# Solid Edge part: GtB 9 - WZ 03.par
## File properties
Author: Carsten
Template: Normal.par
Last saved by: Carsten
Revision: 2
Application: Solid Edge
Genauigkeit: 0,990
Teilflächenrmatvorlage: Model Default
Coef. of Thermal Exp: 0.0
Thermal Conductivity: 0.0
Specific Heat: 0.0
Modulus of Elasticity: 0.0
Poission's Ratio: 0.0
Yield Stress: 0.0
Ultimate Stress: 0.0
Elongation: 0.0
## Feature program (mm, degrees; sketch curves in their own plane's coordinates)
sketch for "unnamed Protrusion 1" plane through (0, 0, 0) normal (1, 0, 0) x-axis (0, 1, 0)
  line (-25.836, 43.4801) -> (-25.836, -41.5199)
  line (-25.836, -41.5199) -> (29.164, -41.5199)
  line (29.164, -41.5199) -> (29.164, 43.4801)
  line (29.164, 43.4801) -> (-25.836, 43.4801)
extrude "unnamed Protrusion 1" add finite 60 along -normal
sketch for "Ausschnitt_1" #1 plane through (0, 1.664, 0.9801) normal (1, 0, 0) x-axis (0, 1, 0)
  line (27.5, -42.5) -> (27.5, -27.5)
  line (27.5, -27.5) -> (17.5, -27.5)
  line (17.5, -27.5) -> (17.5, -42.5)
  line (17.5, -42.5) -> (27.5, -42.5)
sketch for "Ausschnitt_1" #2 plane through (0, 1.664, 0.9801) normal (1, 0, 0) x-axis (0, 1, 0)
  line (-27.5, -42.5) -> (-17.5, -42.5)
  line (-17.5, -42.5) -> (-17.5, -27.5)
  line (-17.5, -27.5) -> (-27.5, -27.5)
  line (-27.5, -27.5) -> (-27.5, -42.5)
extrude "Ausschnitt_1" cut finite 146.05 along -normal
sketch for "Ausschnitt_2" plane through (0, 1.664, 0.9801) normal (1, 0, 0) x-axis (0, 1, 0)
  line (-10, -42.5) -> (-10, -32.5)
  line (-10, -32.5) -> (10, -32.5)
  line (10, -32.5) -> (10, -42.5)
  line (10, -42.5) -> (-10, -42.5)
  dimension (linear) = 10
  dimension (linear) = 10
extrude "Ausschnitt_2" cut finite 107.95 along -normal
sketch for "Ausschnitt_3" #1 plane through (-30, -25.836, 8.4801) normal (0, -1, 0) x-axis (1, 0, 0)
  line (30, 35) -> (30, -15)
  line (25, 35) -> (30, -15)
  line (30, 35) -> (25, 35)
sketch for "Ausschnitt_3" #2 plane through (-30, -25.836, 8.4801) normal (0, -1, 0) x-axis (1, 0, 0)
  line (-30, 35) -> (-25, 35)
  line (-30, -15) -> (-25, 35)
  line (-30, 35) -> (-30, -15)
extrude "Ausschnitt_3" cut finite 82.55 along -normal
sketch for "Ausschnitt_4" plane through (-30, -25.836, 8.4801) normal (0, -1, 0) x-axis (1, 0, 0)
  line (-20, 35) -> (20, 35)
  line (20, 35) -> (20, -30)
  line (20, -30) -> (-20, -30)
  line (-20, -30) -> (-20, 35)
  dimension (linear) = 20
  dimension (linear) = 20
extrude "Ausschnitt_4" cut finite 98.425 along -normal
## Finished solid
Body 1: solid body, 20 faces, 54 edges, 36 vertices.
  Faces by surface: plane 20
  Edges by curve: line 54
Bounding box of the edges (mm): 60.000 x 55.000 x 85.000, from (-60, -25.836, -41.5199) to (0, 29.164, 43.4801).
Planar faces by outward normal: +x 2, +y 3, +z 3, -x 2, -y 3, -z 5, oblique 2
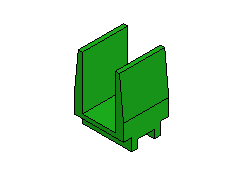
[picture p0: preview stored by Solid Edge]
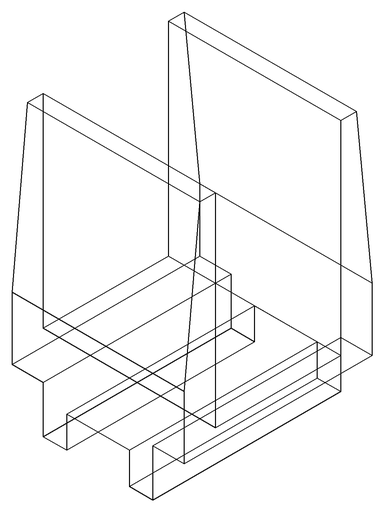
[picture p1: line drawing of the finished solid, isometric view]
